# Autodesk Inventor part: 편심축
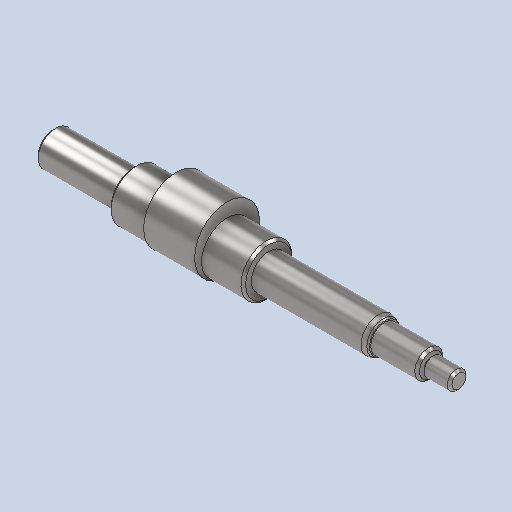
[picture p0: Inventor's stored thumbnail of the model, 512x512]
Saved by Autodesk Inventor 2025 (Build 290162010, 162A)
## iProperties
Created: 2024-07
Part Number: 편심축
Material: 강철, 연강
Document SubType Name: Modeling
Designer: 학생
Density: 7.86 g/cm^3
Appearance: 기본값
Author: jhkim
Sending System: Autodesk Inventor 2025
Preprocessor: ST-DEVELOPER v20
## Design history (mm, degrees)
feature "솔리드1"
node "솔리드2"
